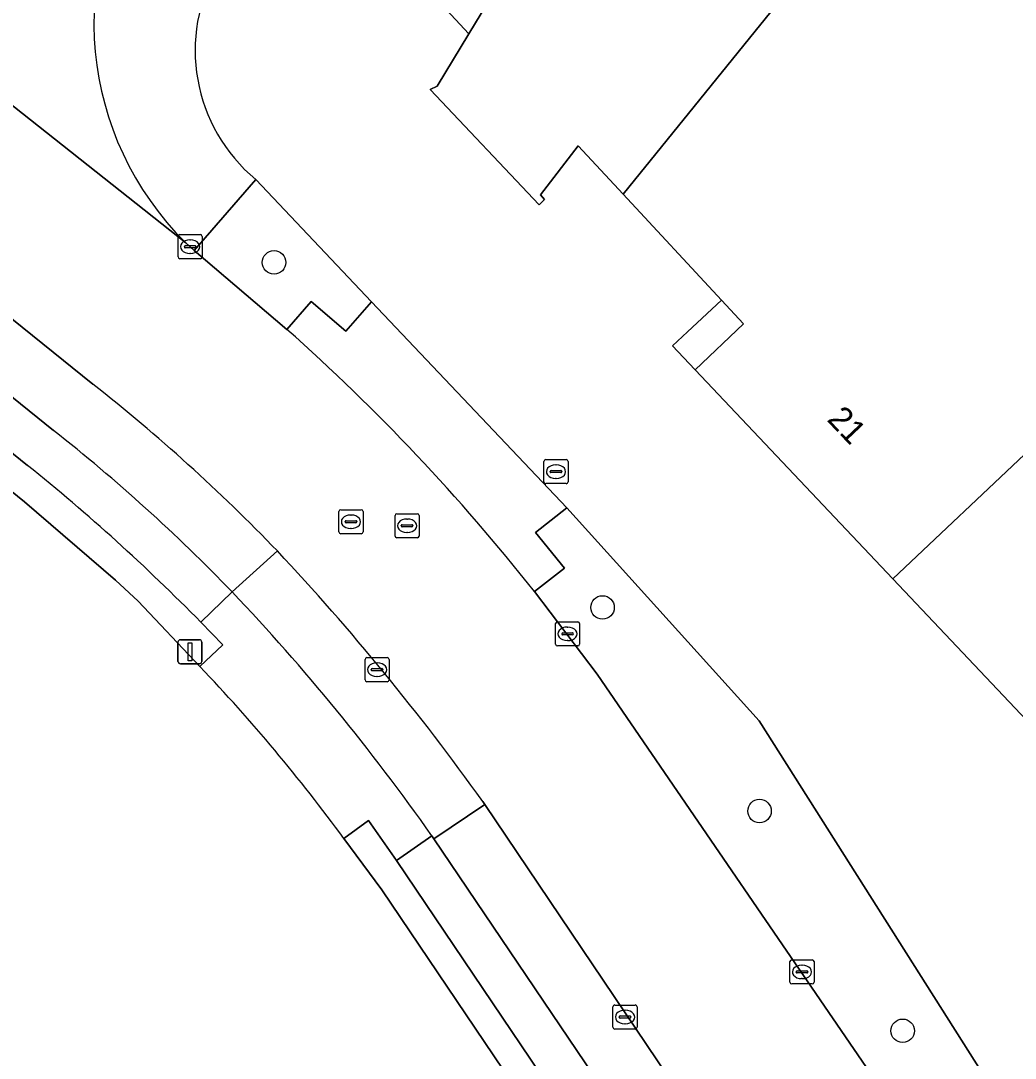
# Model space of a CAD drawing. Extents: x 156702 to 158052, y 387630 to 388992.
# Drawn here: x 157356.49 to 157397.84, y 388025.16 to 388068.29 of the extents above; entities that cross this region are included whole.
import ezdxf

# ---------------------------------------------------------------- set-up
doc = ezdxf.new("R2010")
doc.units = 0
for name, color, linetype in [('IMGEO_Berm_groen', 7, 'Continuous'), ('IMGEO_Boom', 7, 'Continuous'), ('IMGEO_Brandkraan', 7, 'Continuous'), ('IMGEO_Erf', 7, 'Continuous'), ('IMGEO_Groenvoorziening', 7, 'Continuous'), ('IMGEO_Kolk', 7, 'Continuous'), ('IMGEO_Lichtmast', 7, 'Continuous'), ('IMGEO_Pand', 7, 'Continuous'), ('IMGEO_Pand_nummerreeks', 7, 'Continuous'), ('IMGEO_Pand_overbouw', 7, 'Continuous'), ('IMGEO_Parkeervlak_open', 7, 'Continuous'), ('IMGEO_Rijbaan_lokaal_gesloten', 7, 'Continuous'), ('IMGEO_Rijbaan_lokaal_open', 7, 'Continuous'), ('IMGEO_Rioolput', 7, 'Continuous'), ('IMGEO_Voetpad_open', 7, 'Continuous')]:
    doc.layers.add(name, color=color, linetype=linetype)

msp = doc.modelspace()

# ---------------------------------------------------------------- linework, layer by layer
at = {"layer": 'IMGEO_Berm_groen'}
for points in [[(157366.266, 388061.682), (157363.705, 388058.742), (157367.559, 388055.453), (157368.559, 388056.62), (157370.006, 388055.382), (157371.077, 388056.599)], [(157387.19, 388039.182), (157379.198, 388048.04), (157377.897, 388047.012), (157379.097, 388045.532), (157377.848, 388044.562), (157380.459, 388041.129), (157392.527, 388023.508), (157393.764, 388024.429), (157394.61, 388023.215), (157396.502, 388024.511)]]:
    msp.add_lwpolyline(points, close=True, dxfattribs=at)
at = {"layer": 'IMGEO_Boom'}
for centre in [(157367.021, 388058.242), (157380.683, 388043.9), (157387.211, 388035.437), (157393.162, 388026.304)]:
    msp.add_circle(centre, 0.489, dxfattribs=at)
at = {"layer": 'IMGEO_Brandkraan'}
for p, q in [((157378.245, 388049.119), (157378.245, 388049.971)), ((157378.32, 388050.045), (157379.172, 388050.045)), ((157379.246, 388049.971), (157379.246, 388049.119)), ((157378.504, 388049.539), (157378.504, 388049.551)), ((157378.942, 388049.502), (157378.544, 388049.502)), ((157378.547, 388049.588), (157378.945, 388049.588)), ((157378.733, 388049.825), (157378.758, 388049.825)), ((157378.988, 388049.551), (157378.988, 388049.539)), ((157379.172, 388049.045), (157378.32, 388049.045)), ((157378.756, 388049.265), (157378.731, 388049.265))]:
    msp.add_line(p, q, dxfattribs=at)
for points in [[(157378.245, 388049.119), (157378.245, 388049.971)], [(157378.32, 388050.045), (157379.172, 388050.045)], [(157379.246, 388049.971), (157379.246, 388049.119)], [(157379.172, 388049.045), (157378.32, 388049.045)]]:
    msp.add_lwpolyline(points, dxfattribs=at)
for centre, radius, start, end in [((157378.322, 388049.969), 0.0765, 91.552, 178.448), ((157378.322, 388049.969), 0.0765, 91.552, 178.448), ((157379.17, 388049.969), 0.0765, 1.552, 88.448), ((157379.17, 388049.969), 0.0765, 1.552, 88.448), ((157378.544, 388049.548), 0.0403, 85.8775, 175.7526), ((157378.541, 388049.538), 0.0366, 178.938, 274.7102), ((157378.945, 388049.545), 0.043, 264.8664, 352.4533), ((157378.949, 388049.55), 0.0386, 1.7309, 96.639), ((157378.322, 388049.121), 0.0765, 181.552, 268.448), ((157378.322, 388049.121), 0.0765, 181.552, 268.448), ((157379.17, 388049.121), 0.0765, 271.552, 358.448), ((157379.17, 388049.121), 0.0765, 271.552, 358.448)]:
    msp.add_arc(centre, radius, start, end, dxfattribs=at)
for centre, major_axis, ratio, start_param, end_param in [((157378.732, 388049.545), (-0.387, 0.002), 0.722429, 4.712389, 7.853982), ((157378.757, 388049.545), (-0.39, 0.002), 0.717154, 1.570796, 4.712389)]:
    msp.add_ellipse(centre, major_axis=major_axis, ratio=ratio, start_param=start_param, end_param=end_param, dxfattribs=at)
at = {"layer": 'IMGEO_Erf'}
for points in [[(157363.942, 388041.441), (157361.367, 388044.157), (157360.422, 388045.039), (157356.641, 388048.292), (157345.073, 388057.645), (157335.501, 388065.276), (157328.331, 388071.037), (157319.509, 388078.127), (157302.386, 388091.949)], [(157435.268, 388050.312), (157434.011, 388049.475), (157408.437, 388032.449), (157407.831, 388033.213), (157403.926, 388037.312), (157402.98, 388038.304), (157400.975, 388036.406), (157392.75, 388045.095), (157384.534, 388053.774), (157386.548, 388055.693), (157385.632, 388056.676), (157381.537, 388061.074), (157379.662, 388063.087), (157378.097, 388061.046), (157378.275, 388060.85), (157378.044, 388060.636), (157373.516, 388065.423), (157373.801, 388065.569), (157375.12, 388067.746), (157377.791, 388072.155)], [(157366.266, 388061.682), (157371.077, 388056.599), (157379.198, 388048.04), (157387.19, 388039.182), (157396.502, 388024.511)], [(157410.18, 387974.784), (157402.177, 387986.679), (157401.025, 387988.392), (157393.215, 388000), (157371.506, 388032.159), (157369.928, 388034.292)]]:
    msp.add_lwpolyline(points, dxfattribs=at)
for centre, radius, start, end in [((157370.722, 388067.056), 6.981, 149.7161, 230.3307), ((157312.006, 387991.873), 71.793, 36.21683, 43.66339)]:
    msp.add_arc(centre, radius, start, end, dxfattribs=at)
at = {"layer": 'IMGEO_Groenvoorziening'}
msp.add_lwpolyline([(157356.767, 388049.806), (157338.064, 388064.911), (157336.327, 388066.305), (157335.501, 388065.276), (157345.073, 388057.645), (157356.641, 388048.292), (157360.422, 388045.039), (157361.367, 388044.157), (157363.942, 388041.441), (157364.891, 388042.341), (157363.976, 388043.286)], dxfattribs=at)
msp.add_lwpolyline([(157372.113, 388033.384), (157370.953, 388035.05), (157369.928, 388034.292), (157371.506, 388032.159), (157393.215, 388000), (157401.025, 387988.392), (157402.016, 387989.08)], close=True, dxfattribs=at)
msp.add_arc((157305.974, 387986.401), 81.241, 44.4434, 51.30264, dxfattribs=at)
at = {"layer": 'IMGEO_Kolk'}
for p, q in [((157363.107, 388059.394), (157363.959, 388059.394)), ((157363.032, 388058.468), (157363.032, 388059.32)), ((157363.334, 388058.937), (157363.732, 388058.937)), ((157363.52, 388059.174), (157363.545, 388059.174)), ((157364.033, 388059.32), (157364.033, 388058.468)), ((157363.291, 388058.888), (157363.291, 388058.9)), ((157363.729, 388058.851), (157363.331, 388058.851)), ((157363.543, 388058.614), (157363.518, 388058.614)), ((157363.775, 388058.9), (157363.775, 388058.888)), ((157363.959, 388058.394), (157363.107, 388058.394)), ((157378.727, 388042.377), (157378.727, 388043.229)), ((157378.802, 388043.303), (157379.654, 388043.303)), ((157379.215, 388043.083), (157379.24, 388043.083)), ((157379.728, 388043.229), (157379.728, 388042.377)), ((157378.986, 388042.797), (157378.986, 388042.809)), ((157379.424, 388042.76), (157379.026, 388042.76)), ((157379.029, 388042.846), (157379.427, 388042.846)), ((157379.47, 388042.809), (157379.47, 388042.797)), ((157379.654, 388042.303), (157378.802, 388042.303)), ((157379.238, 388042.523), (157379.213, 388042.523)), ((157370.804, 388040.889), (157370.804, 388041.741)), ((157370.879, 388041.815), (157371.731, 388041.815)), ((157371.805, 388041.741), (157371.805, 388040.889)), ((157371.063, 388041.309), (157371.063, 388041.321)), ((157371.501, 388041.272), (157371.103, 388041.272)), ((157371.106, 388041.358), (157371.504, 388041.358)), ((157371.292, 388041.595), (157371.317, 388041.595)), ((157371.547, 388041.321), (157371.547, 388041.309)), ((157371.315, 388041.035), (157371.29, 388041.035)), ((157371.731, 388040.815), (157370.879, 388040.815)), ((157388.475, 388028.326), (157388.475, 388029.178)), ((157388.55, 388029.252), (157389.402, 388029.252)), ((157389.476, 388029.178), (157389.476, 388028.326)), ((157388.734, 388028.746), (157388.734, 388028.758)), ((157388.777, 388028.795), (157389.175, 388028.795)), ((157388.963, 388029.032), (157388.988, 388029.032)), ((157389.218, 388028.758), (157389.218, 388028.746)), ((157389.172, 388028.709), (157388.774, 388028.709)), ((157388.986, 388028.472), (157388.961, 388028.472)), ((157389.402, 388028.252), (157388.55, 388028.252)), ((157381.116, 388026.45), (157381.116, 388027.302)), ((157381.191, 388027.376), (157382.043, 388027.376)), ((157381.604, 388027.156), (157381.629, 388027.156)), ((157382.117, 388027.302), (157382.117, 388026.45)), ((157381.375, 388026.87), (157381.375, 388026.882)), ((157381.813, 388026.833), (157381.415, 388026.833)), ((157381.418, 388026.919), (157381.816, 388026.919)), ((157381.627, 388026.596), (157381.602, 388026.596)), ((157381.859, 388026.882), (157381.859, 388026.87)), ((157382.043, 388026.376), (157381.191, 388026.376))]:
    msp.add_line(p, q, dxfattribs=at)
for points in [[(157363.107, 388059.394), (157363.959, 388059.394)], [(157363.032, 388058.468), (157363.032, 388059.32)], [(157364.033, 388059.32), (157364.033, 388058.468)], [(157363.959, 388058.394), (157363.107, 388058.394)], [(157378.727, 388042.377), (157378.727, 388043.229)], [(157378.802, 388043.303), (157379.654, 388043.303)], [(157379.728, 388043.229), (157379.728, 388042.377)], [(157379.654, 388042.303), (157378.802, 388042.303)], [(157370.804, 388040.889), (157370.804, 388041.741)], [(157370.879, 388041.815), (157371.731, 388041.815)], [(157371.805, 388041.741), (157371.805, 388040.889)], [(157371.731, 388040.815), (157370.879, 388040.815)], [(157388.475, 388028.326), (157388.475, 388029.178)], [(157388.55, 388029.252), (157389.402, 388029.252)], [(157389.476, 388029.178), (157389.476, 388028.326)], [(157389.402, 388028.252), (157388.55, 388028.252)], [(157381.116, 388026.45), (157381.116, 388027.302)], [(157381.191, 388027.376), (157382.043, 388027.376)], [(157382.117, 388027.302), (157382.117, 388026.45)], [(157382.043, 388026.376), (157381.191, 388026.376)]]:
    msp.add_lwpolyline(points, dxfattribs=at)
for centre, radius, start, end in [((157363.109, 388059.318), 0.0765, 91.552, 178.448), ((157363.109, 388059.318), 0.0765, 91.552, 178.448), ((157363.957, 388059.318), 0.0765, 1.552, 88.448), ((157363.957, 388059.318), 0.0765, 1.552, 88.448), ((157363.331, 388058.897), 0.0403, 85.8775, 175.7526), ((157363.736, 388058.899), 0.0386, 1.7309, 96.639), ((157363.328, 388058.887), 0.0366, 178.938, 274.7102), ((157363.732, 388058.894), 0.043, 264.8664, 352.4533), ((157363.109, 388058.47), 0.0765, 181.552, 268.448), ((157363.109, 388058.47), 0.0765, 181.552, 268.448), ((157363.957, 388058.47), 0.0765, 271.552, 358.448), ((157363.957, 388058.47), 0.0765, 271.552, 358.448), ((157378.804, 388043.227), 0.0765, 91.552, 178.448), ((157378.804, 388043.227), 0.0765, 91.552, 178.448), ((157379.652, 388043.227), 0.0765, 1.552, 88.448), ((157379.652, 388043.227), 0.0765, 1.552, 88.448), ((157379.026, 388042.806), 0.0403, 85.8775, 175.7526), ((157379.023, 388042.796), 0.0366, 178.938, 274.7102), ((157379.427, 388042.803), 0.043, 264.8664, 352.4533), ((157379.431, 388042.808), 0.0386, 1.7309, 96.639), ((157378.804, 388042.379), 0.0765, 181.552, 268.448), ((157378.804, 388042.379), 0.0765, 181.552, 268.448), ((157379.652, 388042.379), 0.0765, 271.552, 358.448), ((157379.652, 388042.379), 0.0765, 271.552, 358.448), ((157370.881, 388041.739), 0.0765, 91.552, 178.448), ((157370.881, 388041.739), 0.0765, 91.552, 178.448), ((157371.729, 388041.739), 0.0765, 1.552, 88.448), ((157371.729, 388041.739), 0.0765, 1.552, 88.448), ((157371.103, 388041.318), 0.0403, 85.8775, 175.7526), ((157371.1, 388041.308), 0.0366, 178.938, 274.7102), ((157371.504, 388041.315), 0.043, 264.8664, 352.4533), ((157371.508, 388041.32), 0.0386, 1.7309, 96.639), ((157370.881, 388040.891), 0.0765, 181.552, 268.448), ((157370.881, 388040.891), 0.0765, 181.552, 268.448), ((157371.729, 388040.891), 0.0765, 271.552, 358.448), ((157371.729, 388040.891), 0.0765, 271.552, 358.448), ((157388.552, 388029.176), 0.0765, 91.552, 178.448), ((157388.552, 388029.176), 0.0765, 91.552, 178.448), ((157389.4, 388029.176), 0.0765, 1.552, 88.448), ((157389.4, 388029.176), 0.0765, 1.552, 88.448), ((157388.774, 388028.755), 0.0403, 85.8775, 175.7526), ((157389.179, 388028.757), 0.0386, 1.7309, 96.639), ((157388.552, 388028.328), 0.0765, 181.552, 268.448), ((157388.552, 388028.328), 0.0765, 181.552, 268.448), ((157388.771, 388028.745), 0.0366, 178.938, 274.7102), ((157389.175, 388028.752), 0.043, 264.8664, 352.4533), ((157389.4, 388028.328), 0.0765, 271.552, 358.448), ((157389.4, 388028.328), 0.0765, 271.552, 358.448), ((157381.193, 388027.3), 0.0765, 91.552, 178.448), ((157381.193, 388027.3), 0.0765, 91.552, 178.448), ((157382.041, 388027.3), 0.0765, 1.552, 88.448), ((157382.041, 388027.3), 0.0765, 1.552, 88.448), ((157381.415, 388026.879), 0.0403, 85.8775, 175.7526), ((157381.412, 388026.869), 0.0366, 178.938, 274.7102), ((157381.816, 388026.876), 0.043, 264.8664, 352.4533), ((157381.82, 388026.881), 0.0386, 1.7309, 96.639), ((157381.193, 388026.452), 0.0765, 181.552, 268.448), ((157381.193, 388026.452), 0.0765, 181.552, 268.448), ((157382.041, 388026.452), 0.0765, 271.552, 358.448), ((157382.041, 388026.452), 0.0765, 271.552, 358.448)]:
    msp.add_arc(centre, radius, start, end, dxfattribs=at)
for centre, major_axis, ratio, start_param, end_param in [((157363.519, 388058.894), (-0.387, 0.002), 0.722429, 4.712389, 7.853982), ((157363.544, 388058.894), (-0.39, 0.002), 0.717154, 1.570796, 4.712389), ((157379.214, 388042.803), (-0.387, 0.002), 0.722429, 4.712389, 7.853982), ((157379.239, 388042.803), (-0.39, 0.002), 0.717154, 1.570796, 4.712389), ((157371.291, 388041.315), (-0.387, 0.002), 0.722429, 4.712389, 7.853982), ((157371.316, 388041.315), (-0.39, 0.002), 0.717154, 1.570796, 4.712389), ((157388.962, 388028.752), (-0.387, 0.002), 0.722429, 4.712389, 7.853982), ((157388.987, 388028.752), (-0.39, 0.002), 0.717154, 1.570796, 4.712389), ((157381.603, 388026.876), (-0.387, 0.002), 0.722429, 4.712389, 7.853982), ((157381.628, 388026.876), (-0.39, 0.002), 0.717154, 1.570796, 4.712389)]:
    msp.add_ellipse(centre, major_axis=major_axis, ratio=ratio, start_param=start_param, end_param=end_param, dxfattribs=at)
at = {"layer": 'IMGEO_Lichtmast'}
for p, q in [((157363.126, 388042.56), (157363.916, 388042.56)), ((157363.916, 388042.56), (157363.126, 388042.56)), ((157363.026, 388041.66), (157363.026, 388042.46)), ((157363.026, 388042.46), (157363.026, 388041.66)), ((157364.016, 388042.46), (157364.016, 388041.66)), ((157364.016, 388041.66), (157364.016, 388042.46)), ((157363.916, 388041.56), (157363.126, 388041.56)), ((157363.126, 388041.56), (157363.916, 388041.56))]:
    msp.add_line(p, q, dxfattribs=at)
msp.add_lwpolyline([(157363.446, 388042.435), (157363.596, 388042.435), (157363.596, 388041.685), (157363.446, 388041.685), (157363.446, 388042.435)], dxfattribs=at)
for centre, start, end in [((157363.126, 388042.46), 90, 180), ((157363.126, 388042.46), 90, 180), ((157363.916, 388042.46), 0, 90), ((157363.916, 388042.46), 360, 90), ((157363.126, 388041.66), 180, 270), ((157363.126, 388041.66), 180, 270), ((157363.916, 388041.66), 270, 0), ((157363.916, 388041.66), 270, 0)]:
    msp.add_arc(centre, 0.1, start, end, dxfattribs=at)
at = {"layer": 'IMGEO_Pand'}
for points in [[(157401.351, 388085.55), (157393.215, 388092.187), (157377.518, 388072.763), (157377.317, 388072.514), (157377.791, 388072.155), (157375.12, 388067.746), (157373.801, 388065.569), (157373.516, 388065.423), (157378.044, 388060.636), (157378.275, 388060.85), (157378.097, 388061.046), (157379.662, 388063.087), (157381.537, 388061.074), (157399.778, 388083.607), (157400.684, 388084.726)], [(157401.351, 388085.55), (157400.684, 388084.726), (157399.778, 388083.607), (157381.537, 388061.074), (157385.632, 388056.676), (157386.548, 388055.693), (157384.534, 388053.774), (157392.75, 388045.095), (157398.472, 388050.495), (157399.125, 388049.804), (157409.662, 388059.698), (157413.562, 388063.36), (157417.44, 388067.002), (157407.904, 388077.089), (157408.998, 388078.123), (157401.597, 388085.854)], [(157392.75, 388045.095), (157400.975, 388036.406), (157402.98, 388038.304), (157403.926, 388037.312), (157407.831, 388033.213), (157408.437, 388032.449), (157434.011, 388049.475), (157427.052, 388056.836), (157417.44, 388067.002), (157413.562, 388063.36), (157409.662, 388059.698), (157399.125, 388049.804), (157398.472, 388050.495)]]:
    msp.add_lwpolyline(points, close=True, dxfattribs=at)
at = {"layer": 'IMGEO_Pand_overbouw'}
for points in [[(157377.518, 388072.763), (157377.272, 388072.972), (157374.006, 388068.927), (157375.12, 388067.746), (157377.791, 388072.155), (157377.317, 388072.514)], [(157384.534, 388053.774), (157386.548, 388055.693), (157385.632, 388056.676), (157384.221, 388055.352), (157383.594, 388054.768), (157383.809, 388054.537)]]:
    msp.add_lwpolyline(points, close=True, dxfattribs=at)
at = {"layer": 'IMGEO_Parkeervlak_open'}
for points in [[(157340.763, 388068.274), (157339.186, 388066.318), (157357.849, 388051.255)], [(157359.484, 388053.181), (157340.763, 388068.274)], [(157365.278, 388044.547), (157367.159, 388046.248)], [(157375.784, 388035.713), (157373.667, 388034.286), (157409.026, 387981.971)], [(157412.951, 387980.565), (157375.784, 388035.713)]]:
    msp.add_lwpolyline(points, dxfattribs=at)
for centre, radius, start, end in [((157313.542, 387994.607), 74.442, 43.92434, 51.89124), ((157312.751, 387993.842), 73.008, 43.98891, 51.85031)]:
    msp.add_arc(centre, radius, start, end, dxfattribs=at)
at = {"layer": 'IMGEO_Rijbaan_lokaal_gesloten'}
for points in [[(157397.82, 388130.747), (157372.577, 388099.512), (157356.41, 388079.268), (157355.48, 388078.115), (157354.015, 388076.833), (157353.016, 388076.181), (157352.205, 388075.752), (157350.909, 388075.228), (157349.26, 388074.812), (157347.485, 388074.649), (157346.364, 388074.69), (157345.672, 388074.796), (157344.981, 388074.902), (157344.863, 388074.92), (157343.374, 388075.363), (157341.899, 388076.038), (157363.348, 388059.054)], [(157341.899, 388076.038), (157338.534, 388071.878), (157341.664, 388069.346), (157340.735, 388068.296), (157340.763, 388068.274), (157359.484, 388053.181)], [(157367.559, 388055.453), (157363.705, 388058.742), (157363.348, 388059.054), (157341.899, 388076.038)], [(157375.701, 388035.836), (157375.784, 388035.713), (157412.951, 387980.565), (157414.43, 387978.195), (157420.098, 387982.532), (157416.586, 387987.739), (157407.925, 388000.59), (157400.555, 388011.557), (157392.527, 388023.508), (157380.459, 388041.129), (157377.848, 388044.562)]]:
    msp.add_lwpolyline(points, dxfattribs=at)
for centre, radius, start, end in [((157372.416, 388068.209), 12.886, 145.5686, 225.272), ((157311.212, 387991.915), 84.924, 38.3112, 48.43264), ((157313.542, 387994.607), 74.442, 43.92434, 51.89124), ((157292.705, 387976.456), 102.05, 35.58202, 43.14886)]:
    msp.add_arc(centre, radius, start, end, dxfattribs=at)
at = {"layer": 'IMGEO_Rijbaan_lokaal_open'}
msp.add_lwpolyline([(157377.848, 388044.562), (157379.097, 388045.532), (157377.897, 388047.012), (157379.198, 388048.04), (157371.077, 388056.599), (157370.006, 388055.382), (157368.559, 388056.62), (157367.559, 388055.453)], dxfattribs=at)
msp.add_arc((157311.212, 387991.915), 84.924, 38.3112, 48.43264, dxfattribs=at)
at = {"layer": 'IMGEO_Rioolput'}
for p, q in [((157369.72, 388047.036), (157369.72, 388047.888)), ((157369.795, 388047.962), (157370.647, 388047.962)), ((157370.208, 388047.742), (157370.233, 388047.742)), ((157370.721, 388047.888), (157370.721, 388047.036)), ((157372.054, 388046.869), (157372.054, 388047.721)), ((157372.129, 388047.795), (157372.981, 388047.795)), ((157373.055, 388047.721), (157373.055, 388046.869)), ((157369.979, 388047.456), (157369.979, 388047.468)), ((157370.417, 388047.419), (157370.019, 388047.419)), ((157370.022, 388047.505), (157370.42, 388047.505)), ((157370.463, 388047.468), (157370.463, 388047.456)), ((157372.313, 388047.289), (157372.313, 388047.301)), ((157372.356, 388047.338), (157372.754, 388047.338)), ((157372.542, 388047.575), (157372.567, 388047.575)), ((157372.797, 388047.301), (157372.797, 388047.289)), ((157370.647, 388046.962), (157369.795, 388046.962)), ((157370.231, 388047.182), (157370.206, 388047.182)), ((157372.751, 388047.252), (157372.353, 388047.252)), ((157372.565, 388047.015), (157372.54, 388047.015)), ((157372.981, 388046.795), (157372.129, 388046.795))]:
    msp.add_line(p, q, dxfattribs=at)
for points in [[(157369.72, 388047.036), (157369.72, 388047.888)], [(157369.795, 388047.962), (157370.647, 388047.962)], [(157370.721, 388047.888), (157370.721, 388047.036)], [(157372.054, 388046.869), (157372.054, 388047.721)], [(157372.129, 388047.795), (157372.981, 388047.795)], [(157373.055, 388047.721), (157373.055, 388046.869)], [(157370.647, 388046.962), (157369.795, 388046.962)], [(157372.981, 388046.795), (157372.129, 388046.795)]]:
    msp.add_lwpolyline(points, dxfattribs=at)
for centre, radius, start, end in [((157369.797, 388047.886), 0.0765, 91.552, 178.448), ((157369.797, 388047.886), 0.0765, 91.552, 178.448), ((157370.645, 388047.886), 0.0765, 1.552, 88.448), ((157370.645, 388047.886), 0.0765, 1.552, 88.448), ((157372.131, 388047.719), 0.0765, 91.552, 178.448), ((157372.131, 388047.719), 0.0765, 91.552, 178.448), ((157372.979, 388047.719), 0.0765, 1.552, 88.448), ((157372.979, 388047.719), 0.0765, 1.552, 88.448), ((157370.019, 388047.465), 0.0403, 85.8775, 175.7526), ((157370.016, 388047.455), 0.0366, 178.938, 274.7102), ((157370.42, 388047.462), 0.043, 264.8664, 352.4533), ((157370.424, 388047.467), 0.0386, 1.7309, 96.639), ((157372.353, 388047.298), 0.0403, 85.8775, 175.7526), ((157372.758, 388047.3), 0.0386, 1.7309, 96.639), ((157369.797, 388047.038), 0.0765, 181.552, 268.448), ((157369.797, 388047.038), 0.0765, 181.552, 268.448), ((157370.645, 388047.038), 0.0765, 271.552, 358.448), ((157370.645, 388047.038), 0.0765, 271.552, 358.448), ((157372.131, 388046.871), 0.0765, 181.552, 268.448), ((157372.131, 388046.871), 0.0765, 181.552, 268.448), ((157372.35, 388047.288), 0.0366, 178.938, 274.7102), ((157372.754, 388047.295), 0.043, 264.8664, 352.4533), ((157372.979, 388046.871), 0.0765, 271.552, 358.448), ((157372.979, 388046.871), 0.0765, 271.552, 358.448)]:
    msp.add_arc(centre, radius, start, end, dxfattribs=at)
for centre, major_axis, ratio, start_param, end_param in [((157370.207, 388047.462), (-0.387, 0.002), 0.722429, 4.712389, 7.853982), ((157370.232, 388047.462), (-0.39, 0.002), 0.717154, 1.570796, 4.712389), ((157372.541, 388047.295), (-0.387, 0.002), 0.722429, 4.712389, 7.853982), ((157372.566, 388047.295), (-0.39, 0.002), 0.717154, 1.570796, 4.712389)]:
    msp.add_ellipse(centre, major_axis=major_axis, ratio=ratio, start_param=start_param, end_param=end_param, dxfattribs=at)
at = {"layer": 'IMGEO_Voetpad_open'}
for points in [[(157357.849, 388051.255), (157339.186, 388066.318), (157338.064, 388064.911), (157356.767, 388049.806)], [(157363.348, 388059.054), (157363.705, 388058.742), (157366.266, 388061.682)], [(157367.159, 388046.248), (157365.278, 388044.547)], [(157365.278, 388044.547), (157363.976, 388043.286), (157364.891, 388042.341), (157363.942, 388041.441)], [(157363.976, 388043.286), (157365.278, 388044.547)], [(157373.583, 388034.411), (157373.667, 388034.286), (157375.784, 388035.713), (157375.701, 388035.836)], [(157369.928, 388034.292), (157370.953, 388035.05), (157372.113, 388033.384), (157373.583, 388034.411)], [(157409.026, 387981.971), (157373.667, 388034.286), (157373.583, 388034.411), (157372.113, 388033.384), (157402.016, 387989.08), (157401.025, 387988.392), (157402.177, 387986.679), (157403.198, 387987.328), (157411.206, 387975.464), (157410.18, 387974.784)]]:
    msp.add_lwpolyline(points, dxfattribs=at)
for centre, radius, start, end in [((157372.416, 388068.209), 12.886, 145.5686, 225.272), ((157370.722, 388067.056), 6.981, 149.7161, 230.3307), ((157312.751, 387993.842), 73.008, 43.98891, 51.85031), ((157305.974, 387986.401), 81.241, 44.4434, 51.30264), ((157292.705, 387976.456), 102.05, 35.58202, 43.14886), ((157300.699, 387983.163), 89.098, 35.11259, 43.54682), ((157300.699, 387983.163), 89.098, 35.11259, 43.54682), ((157312.006, 387991.873), 71.793, 36.21683, 43.66339)]:
    msp.add_arc(centre, radius, start, end, dxfattribs=at)

# ---------------------------------------------------------------- texts
at = {"layer": 'IMGEO_Pand_nummerreeks'}
msp.add_text('21', height=1, rotation=313.4302, dxfattribs=at).set_placement((157389.982, 388051.684))

doc.saveas('drawing.dxf')
